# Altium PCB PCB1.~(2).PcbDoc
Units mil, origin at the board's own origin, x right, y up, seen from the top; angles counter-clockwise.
Board outline 6000 x 4000 mil, 2 copper layers (Top Layer, Bottom Layer); 27 components, 22 nets, 73 pads, 0 vias.
Unrouted connection lines stored in the file: 50.
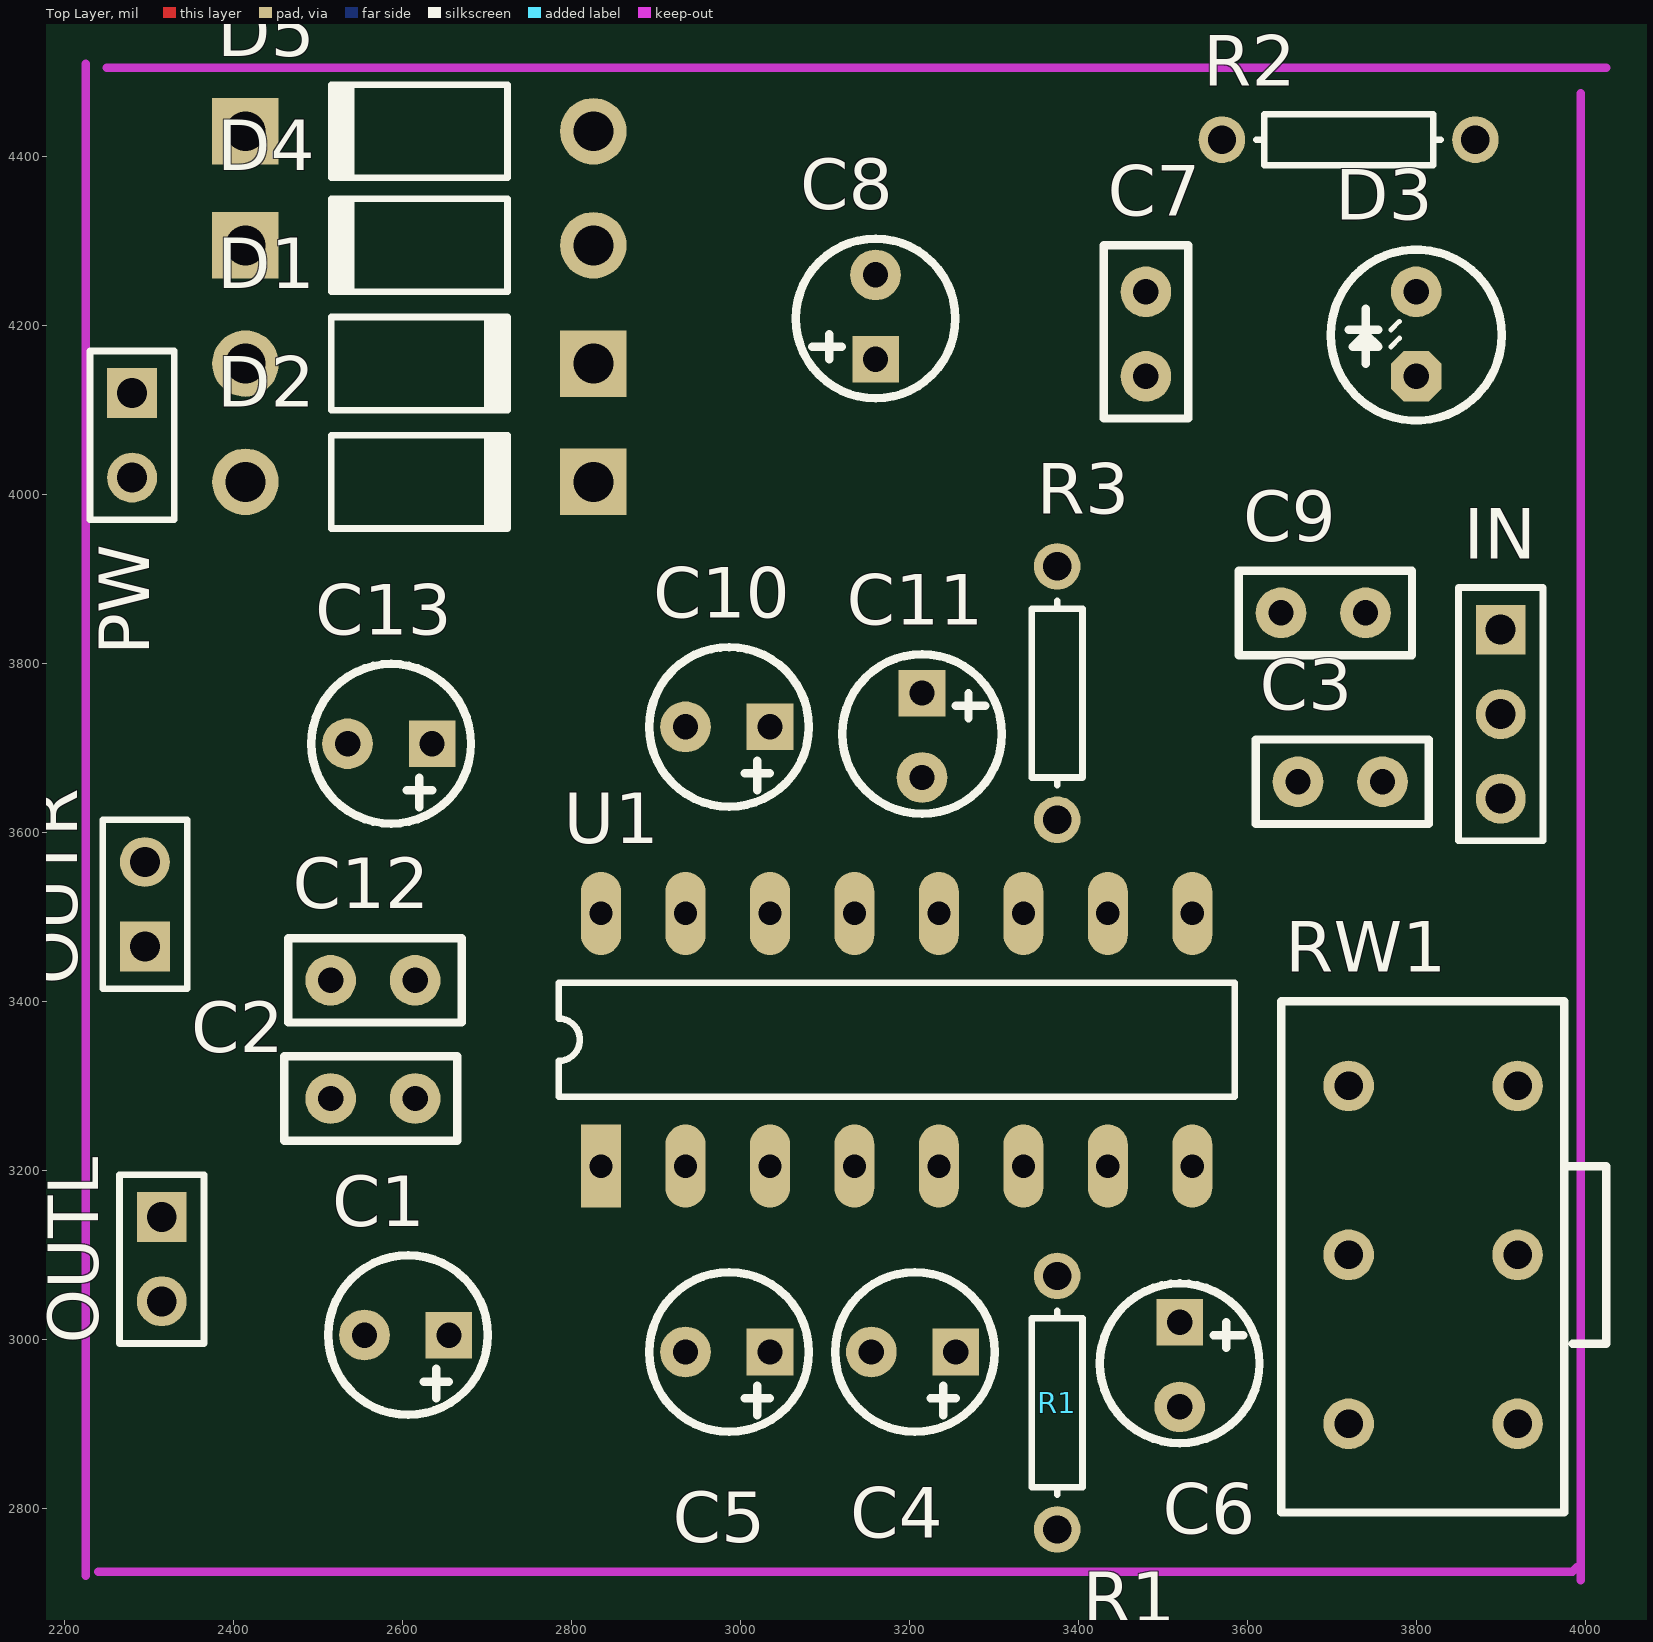
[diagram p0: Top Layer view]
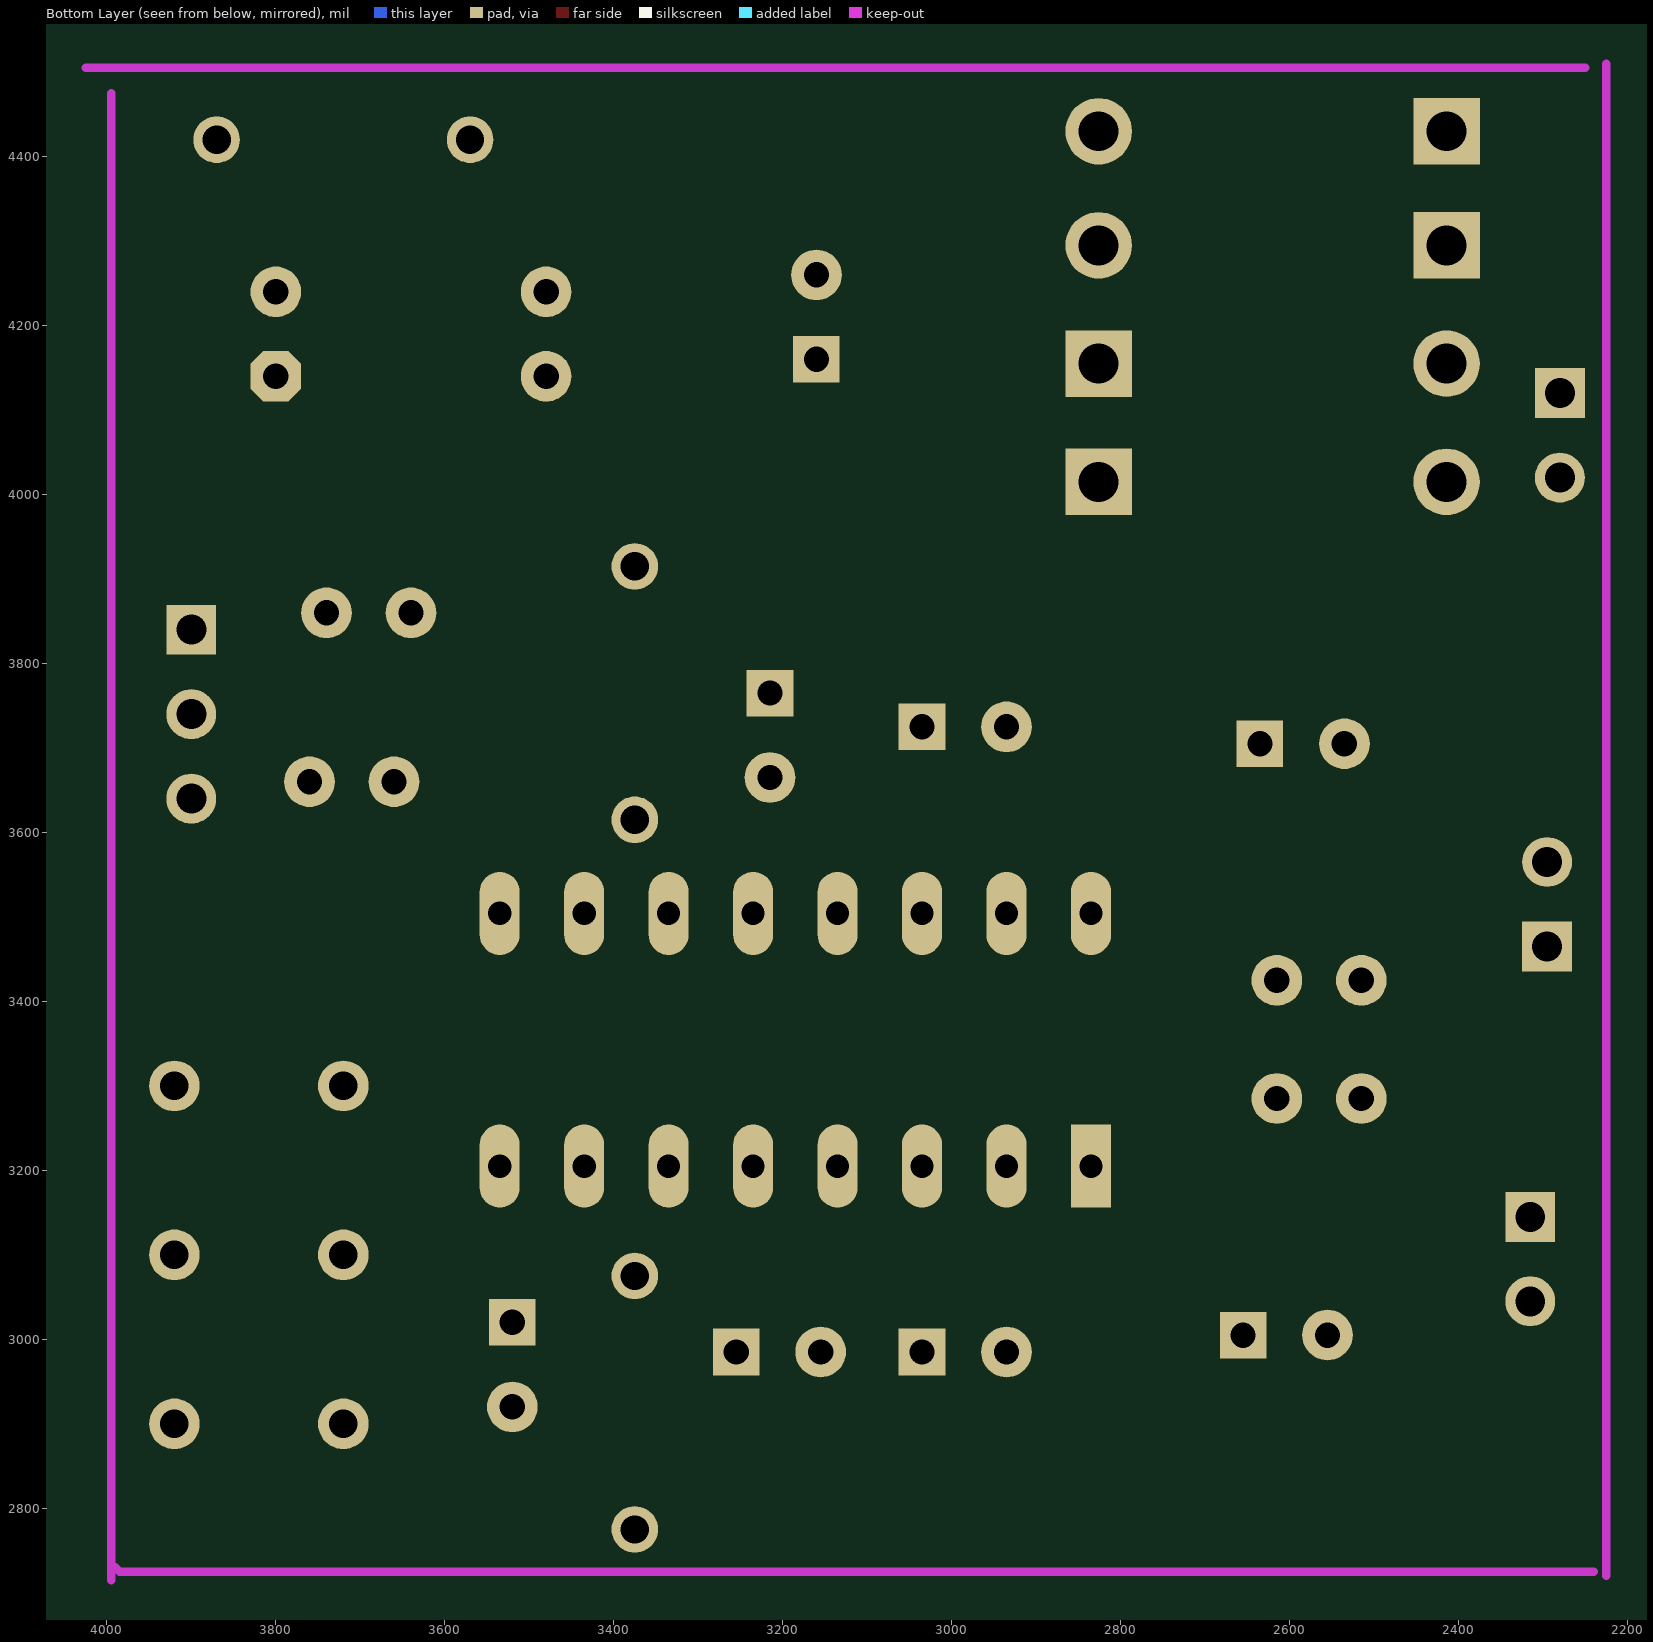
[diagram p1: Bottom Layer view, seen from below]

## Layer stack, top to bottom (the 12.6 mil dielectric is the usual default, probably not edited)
Top Layer: signal copper 1.4
Dielectric: dielectric 12.6, FR-4, Dk 4.8
Bottom Layer: signal copper 1.4

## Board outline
1000,1000 7000,1000 7000,5000 1000,5000

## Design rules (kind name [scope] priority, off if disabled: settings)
Clearance [All] p1: gap=10
PolygonConnect [All] p1: connectstyle=Relief reliefconductorwidth=10 reliefentries=4 polygonreliefangle="90 Angle"
RoutingVias [All] p1: holewidth=28 width=50 viastyle="Through Hole" minholewidth=28 minwidth=50 maxholewidth=28 maxwidth=50
SilkscreenOverComponentPads [All] p1: minsilkscreentomaskgap=10
SolderMaskExpansion [All] p1: expansion=4
Width [All] p1: maxlimit=10 minlimit=10 preferedwidth=10
27 further rules are at their usual default settings.

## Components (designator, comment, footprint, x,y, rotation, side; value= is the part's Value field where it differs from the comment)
C1 "470u" CF0.1 2655,3005 r180 top
C2 "0.1u" RAD0.1 2515,3285 r0 top
C3 "0.22" RAD0.1 3760,3660 r180 top
C4 "100u" CF0.1 3255,2985 r180 top
C5 "100u" CF0.1 3035,2985 r180 top
C6 "100u" CF0.1 3520,3020 r270 top
C7 "Cap" RAD0.1 3480,4240 r270 top
C8 "CF" CF0.1 3160,4160 r90 top
C9 "0.22" RAD0.1 3740,3860 r180 top
C10 "100u" CF0.1 3035,3725 r180 top
C11 "100u" CF0.1 3215,3765 r270 top
C12 "0.1u" RAD0.1 2615,3425 r180 top
C13 "470u" CF0.1 2635,3705 r180 top
D1 "Diode 1N4007" DIO10.46-5.3x2.8 2620,4155 r0 top
D2 "Diode 1N4007" DIO10.46-5.3x2.8 2620,4015 r0 top
D3 "LED0" LED 3800,4140 r90 top
D4 "Diode 1N4007" DIO10.46-5.3x2.8 2620,4295 r180 top
D5 "Diode 1N4007" DIO10.46-5.3x2.8 2620,4430 r180 top
IN "" HDR1X3 3900,3840 r270 top
OUTL "Header 2" HDR1X2 2315,3145 r270 top
OUTR "Header 2" HDR1X2 2295,3465 r90 top
PW "Header 2" HDR1X2 2280,4120 r270 top
R1 "1k" AXIAL-0.3 3375,2925 r270 top
R2 "Res" AXIAL-0.3 3720,4420 r0 top
R3 "1k" AXIAL-0.3 3375,3765 r270 top
RW1 "RW" RW 3920,2900 r180 top
U1 "TEA2025" DIP16 2835,3205 r90 top

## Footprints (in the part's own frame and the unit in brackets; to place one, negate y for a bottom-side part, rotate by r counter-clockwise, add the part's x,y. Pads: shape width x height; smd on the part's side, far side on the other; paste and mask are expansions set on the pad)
AXIAL-0.3 [mm] "Axial Device, Thru-Hole; 2 Leads; 0.3 in Pin Spacing"
  round 1.4 hole 0.85: 1(-3.81,0) 2(3.81,0)
  silkscreen extent -2.77,-0.76 2.77,0.76
CF0.1 [mil]
  rect 55.12x55.12 hole 30: 1(0,0)
  round 60 hole 30: 2(100,0)
  silkscreen extent -46,-94 143,94
DIO10.46-5.3x2.8 [mm] "Diode, Axial; Body 5.2 x 2.7 mm (LxDia. max), Lead Dia. 0.86 mm (max)"
  round 2 hole 1.2: 1(-5.23,0)
  rect 2x2 hole 1.2: 2(5.23,0)
  silkscreen extent -2.65,-1.4 2.75,1.4
DIP16 [mm]
  rect 2.5x1.2 hole 0.7: 1(0,0)
  oval 2.5x1.2 hole 0.7: 2(0,-2.54) 3(0,-5.08) 4(0,-7.62) 5(0,-10.16) 6(0,-12.7) 7(0,-15.24) 8(0,-17.78) 9(7.6,-17.78) 10(7.6,-15.24) 11(7.6,-12.7) 12(7.6,-10.16) 13(7.6,-7.62) 14(7.6,-5.08) 15(7.6,-2.54) 16(7.6,0)
  silkscreen extent 2.08,-19.05 5.52,1.27
HDR1X2 [mm] "Connector; Header; 2 Position"
  rect 1.5x1.5 hole 0.9: 1(0,0)
  round 1.5 hole 0.9: 2(2.54,0)
  silkscreen extent -1.27,-1.27 3.81,1.27
HDR1X3 [mm] "Connector; Header; 3 Position"
  rect 1.5x1.5 hole 0.9: 1(0,0)
  round 1.5 hole 0.9: 2(2.54,0) 3(5.08,0)
  silkscreen extent -1.27,-1.27 6.35,1.27
LED [mil]
  oct 60x60 hole 30: 1(0,0)
  round 60 hole 30: 2(100,0)
  silkscreen extent -52,-101 150,101
RAD0.1 [mil]
  round 60 hole 30: 1(0,0) 2(100,0)
  silkscreen extent -55,-50 150,50
RW [mil]
  round 60 hole 33.94: 1(0,0) 2(0,-200) 3(0,-400) 4(200,0) 5(200,-200) 6(200,-400)
  silkscreen extent -105,-500 280,105

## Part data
C1 C13: library part CF
C2 C3 C9 C12: library part Cap
C4 C5 C6 C10 C11: library part "Cap Pol"
D1 D2 D4 D5: "1 Amp General Purpose Rectifier"
IN: library part "Header 3H", "Header, 3-Pin, Right Angle"
OUTL OUTR PW: "Header, 2-Pin"
R1 R3: library part Res, "Resistor"
R2: "Resistor"

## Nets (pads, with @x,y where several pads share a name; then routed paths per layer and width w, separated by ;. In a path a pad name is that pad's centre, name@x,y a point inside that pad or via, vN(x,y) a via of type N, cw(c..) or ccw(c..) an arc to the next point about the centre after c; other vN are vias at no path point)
GND: C2.1 C4.2 C6.2 C7.1 C8.2 C11.2 C12.2 D4.1 D5.1 IN.2 OUTL.1 OUTR.1 R2.1 RW1.1 RW1.4 U1.4 U1.5 U1.9 U1.12 U1.13
NetC1_1: C1.1 C2.2 C5.2 U1.2
NetC1_2: C1.2 OUTL.2
NetC3_1: C3.1 RW1.2
NetC3_2: C3.2 U1.7
NetC4_1: C4.1 R1.2
NetC5_1: C5.1 U1.3
NetC6_1: C6.1 U1.8
NetC9_1: C9.1 RW1.5
NetC9_2: C9.2 U1.10
NetC10_1: C10.1 U1.14
NetC10_2: C10.2 C12.1 C13.1 U1.15
NetC11_1: C11.1 R3.1
NetC13_2: C13.2 OUTR.2
NetD1_1: D1.1 D4.2 PW.1
NetD2_1: D2.1 D5.2 PW.2
NetD3_2: D3.2 R2.2
NetIN_1: IN.1 RW1.6
NetIN_3: IN.3 RW1.3
NetR1_1: R1.1 U1.6
NetR3_2: R3.2 U1.11
VCC: C7.2 C8.1 D1.2 D2.2 D3.1 U1.16
pads on no net: U1.1

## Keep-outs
Keep-Out Layer:
  lines w10: 2225,2720 2225,4510 ; 2240,2725 3985,2725 3990,2730 ; 2250,4505 4025,4505 ; 3995,2715 3995,4475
